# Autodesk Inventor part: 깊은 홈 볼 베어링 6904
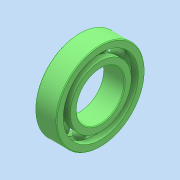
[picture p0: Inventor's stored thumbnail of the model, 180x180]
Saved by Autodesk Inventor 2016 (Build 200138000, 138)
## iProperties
Created: 2024-08
Part Number: 깊은 홈 볼 베어링 6904
Material: 일반
Description: 깊은 그루브 볼 베어링
Document SubType Name: Modeling
Designer: pc-7
Density: 1 g/cm^3
Appearance: 기본값
Author: jhkim
Sending System: Autodesk Inventor 2025
Preprocessor: ST-DEVELOPER v20
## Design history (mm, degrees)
node "깊은 홈 볼 베어링 69041"
node "솔리드1"
node "솔리드2"
node "솔리드3"
node "솔리드4"
node "솔리드5"
node "솔리드6"
node "솔리드7"
node "솔리드8"
node "솔리드9"
node "솔리드10"
node "솔리드11"
node "솔리드12"
body "Solid1"
node "Solid1:1"
node "Solid1:2"
node "Solid1:3"
node "Solid1:4"
node "Solid1:5"
node "Solid1:6"
node "Solid1:7"
node "Solid1:8"
node "Solid1:9"
node "Solid1:10"
node "Solid1:11"
